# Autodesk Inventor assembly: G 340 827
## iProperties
Created: 2006-10
Part Number: G 340 827
Document SubType Name: Assembly
Designer: I.Baliuc
Manufacturer: Standard
Standards Organization: Custom
Description: Hauptkontakt - DC
Mass: 348.311 g
Surface Area: 118.444 cm^2
Volume: 38.8857 cm^3
Density: 8.95729 g/cm^3
Title: DC - Hauptkontakt
Company: Mayer & Müller AG Schaltgeräte
Zweck: 3150A + HSLT (Links/Rechts)
Author: T.Messerschmitt
Revision Number: 340827
